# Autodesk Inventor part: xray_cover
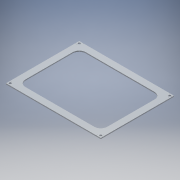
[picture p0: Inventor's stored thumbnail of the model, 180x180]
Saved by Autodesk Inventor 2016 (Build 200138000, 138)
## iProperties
Created: 2015-11
Part Number: xray_cover
Material: Generic
Document SubType Name: Modeling
Designer: t_silvdo
Density: 1 g/cm^3
Appearance: Default
Author: t_silvdo
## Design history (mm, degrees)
sketch "Sketch2"
  geometry: L1 (0, 0)-(279.4, 0); L2 (279.4, 0)-(279.4, -215.9); L3 (279.4, -215.9)-(0, -215.9); L4 (0, -215.9)-(0, 0); C1 r 3.175 at (273.05, -6.35); C2 r 3.175 at (273.05, -209.55); C3 r 3.175 at (6.35, -6.35); C4 r 3.175 at (6.35, -209.55); 1 further point
  constraints: 8 end point, 4 centre point, 2 parallel, 1 horizontal, 1 perpendicular
  dimensions: "d7" = 279.4 distance of L2.end L3.end; "d8" = 215.9 distance of L1.end L2.end; "d9" = 6.35 diameter of C1; "d10" = 6.35 distance from line of C1.centre L1; "d11" = 6.35 distance from line of C1.centre L2
extrude "Extrusion2" new body sketch "Sketch2" distance "d12" = 3 (= acrylic); taper "d13" = 0 deg
sketch "Sketch3"
  geometry: L1 (-279.4, 0)-(0, 0) reference; L2 (0, 0)-(0, 215.9) reference; L3 (0, 215.9)-(-279.4, 215.9) reference; L4 (-279.4, 215.9)-(-279.4, 0) reference; L5 (-38.1, 19.05)-(-241.3, 19.05); L6 (-260.35, 38.1)-(-260.35, 177.8); L7 (-241.3, 196.85)-(-38.1, 196.85); L8 (-19.05, 177.8)-(-19.05, 38.1); L9 (-19.05, 19.05)-(-260.35, 196.85); L10 (-260.35, 19.05)-(-19.05, 196.85); C1 r 3.175 at (-6.35, 209.55) reference; C2 r 3.175 at (-6.35, 6.35) reference; C3 r 3.175 at (-273.05, 209.55) reference; C4 r 3.175 at (-273.05, 6.35) reference; A1 r 19.05 centre (-241.3, 38.1) between (-260.35, 38.1) and (-241.3, 19.05); A2 r 19.05 centre (-241.3, 177.8) between (-241.3, 196.85) and (-260.35, 177.8); A3 r 19.05 centre (-38.1, 177.8) between (-19.05, 177.8) and (-38.1, 196.85); A4 r 19.05 centre (-38.1, 38.1) between (-38.1, 19.05) and (-19.05, 38.1); 2 further points
  constraints: 12 end point, 8 point on circle, 8 point on line, 8 tangent, 4 centre point, 3 equal radius, 2 midpoint, 2 parallel, 1 horizontal, 1 perpendicular
  dimensions: "d14" = 241.3 distance of L9.end L10.end; "d15" = 177.8 distance of L10.start L9.end; "d16" = 19.05 radius of A1
extrude "Extrusion3" cut sketch "Sketch3" distance "d17" = 25.4; taper "d18" = 0 deg
sketch "Sketch5"
  geometry: L1 (-260.35, 38.1)-(-260.35, 177.8) reference; L2 (-241.3, 196.85)-(-38.1, 196.85) reference; L3 (-19.05, 177.8)-(-19.05, 38.1) reference; L4 (-38.1, 19.05)-(-241.3, 19.05) reference; L5 (-279.4, 0)-(0, 0) reference; L6 (0, 0)-(0, 215.9) reference; L7 (0, 215.9)-(-279.4, 215.9) reference; L8 (-279.4, 215.9)-(-279.4, 0) reference; L9 (0, 0)-(0, 215.9) reference; L10 (0, 203.2)-(-4.763, 203.2); L11 (-4.763, 203.2)-(-4.762, 202.946); L12 (-4.762, 202.946)-(0, 202.946); L13 (0, 202.946)-(0, 203.2); L14 (-139.7, 107.95)-(-133.006, 107.95); L15 (-139.7, 107.95)-(-139.7, 101.651); L16 (0, 12.7)-(-4.762, 12.7); L17 (-4.762, 12.7)-(-4.762, 12.954); L18 (-4.762, 12.954)-(0, 12.954); L19 (0, 12.954)-(0, 12.7); L20 (-279.4, 203.2)-(-274.638, 203.2); L21 (-274.638, 203.2)-(-274.638, 202.946); L22 (-274.638, 202.946)-(-279.4, 202.946); L23 (-279.4, 202.946)-(-279.4, 203.2); L24 (-279.4, 215.9)-(-279.4, 0) reference; L25 (-279.4, 12.7)-(-274.637, 12.7); L26 (-274.637, 12.7)-(-274.637, 12.954); L27 (-274.637, 12.954)-(-279.4, 12.954); L28 (-279.4, 12.954)-(-279.4, 12.7); C1 r 3.175 at (-6.35, 209.55) reference; C2 r 3.175 at (-6.35, 6.35) reference; C3 r 3.175 at (-273.05, 209.55) reference; C4 r 3.175 at (-273.05, 6.35) reference; A1 r 19.05 centre (-241.3, 38.1) between (-260.35, 38.1) and (-241.3, 19.05) reference; A2 r 19.05 centre (-241.3, 177.8) between (-241.3, 196.85) and (-260.35, 177.8) reference; A3 r 19.05 centre (-38.1, 177.8) between (-19.05, 177.8) and (-38.1, 196.85) reference; A4 r 19.05 centre (-38.1, 38.1) between (-38.1, 19.05) and (-19.05, 38.1) reference
  constraints: 36 end point, 8 parallel, 5 horizontal, 4 perpendicular, 4 point on line, 1 vertical
  dimensions: "d29" = 4.7625 distance of L12.end L11.end; "d30" = 0.254 distance of L11.end L10.end; "d31" = 6.35 distance from line of C1.centre L10; "d32" = 4.7625 distance of L17.end L18.end; "d33" = 0.254 distance of L16.end L17.end; "d34" = 6.35 distance from line of L16 C2.centre; "d35" = 4.7625 distance of L21.end L22.end; "d36" = 0.254 distance of L20.end L21.end; "d37" = 6.35 distance from line of C3.centre L20; "d38" = 4.7625 distance of L27.end L26.end; "d39" = 0.254 distance of L26.end L25.end; "d40" = 6.35 distance from line of C4.centre L25
extrude "Extrusion5" join sketch "Sketch5" distance "d41" = 0.254; taper "d42" = 0 deg
sketch "Sketch6"
  geometry: L1 (-274.638, 202.946)-(-279.4, 202.946) reference; L2 (-279.4, 202.946)-(-279.4, 12.954) reference; L3 (-279.4, 12.954)-(-274.637, 12.954) reference; L4 (-274.637, 12.954)-(-274.637, 12.7) reference; L5 (-274.637, 12.7)-(-279.4, 12.7) reference; L6 (-279.4, 12.7)-(-279.4, 0) reference; L7 (-279.4, 0)-(0, 0) reference; L8 (0, 0)-(0, 12.7) reference; L9 (0, 12.7)-(-4.762, 12.7) reference; L10 (-4.762, 12.7)-(-4.762, 12.954) reference; L11 (-4.762, 12.954)-(0, 12.954) reference; L12 (0, 12.954)-(0, 202.946) reference; L13 (0, 202.946)-(-4.762, 202.946) reference; L14 (-4.762, 202.946)-(-4.763, 203.2) reference; L15 (-4.763, 203.2)-(0, 203.2) reference; L16 (0, 203.2)-(0, 215.9) reference; L17 (0, 215.9)-(-279.4, 215.9) reference; L18 (-279.4, 215.9)-(-279.4, 203.2) reference; L19 (-279.4, 203.2)-(-274.638, 203.2) reference; L20 (-274.638, 203.2)-(-274.638, 202.946) reference; L21 (-260.35, 38.1)-(-260.35, 177.8) reference; L22 (-241.3, 196.85)-(-38.1, 196.85) reference; L23 (-19.05, 177.8)-(-19.05, 38.1) reference; L24 (-38.1, 19.05)-(-241.3, 19.05) reference; L25 (0, 215.9)-(-279.4, 215.9) reference; L26 (-266.7, 215.9)-(-266.446, 215.9); L27 (-266.446, 215.9)-(-266.446, 211.138); L28 (-266.446, 211.138)-(-266.7, 211.138); L29 (-266.7, 211.138)-(-266.7, 215.9); L30 (-12.7, 215.9)-(-12.954, 215.9); L31 (-12.954, 215.9)-(-12.954, 212.884); L32 (-12.954, 212.884)-(-12.7, 212.884); L33 (-12.7, 212.884)-(-12.7, 215.9); L34 (-279.4, 0)-(0, 0) reference; L35 (-12.954, 0)-(-12.7, 0); L36 (-12.7, 0)-(-12.7, 4.763); L37 (-12.7, 4.763)-(-12.954, 4.763); L38 (-12.954, 4.763)-(-12.954, 0); L39 (-266.7, 0)-(-266.446, 0); L40 (-266.446, 0)-(-266.446, 4.763); L41 (-266.446, 4.763)-(-266.7, 4.763); L42 (-266.7, 4.763)-(-266.7, 0); C1 r 3.175 at (-6.35, 209.55) reference; C2 r 3.175 at (-6.35, 6.35) reference; C3 r 3.175 at (-273.05, 209.55) reference; C4 r 3.175 at (-273.05, 6.35) reference; A1 r 19.05 centre (-241.3, 38.1) between (-260.35, 38.1) and (-241.3, 19.05) reference; A2 r 19.05 centre (-241.3, 177.8) between (-241.3, 196.85) and (-260.35, 177.8) reference; A3 r 19.05 centre (-38.1, 177.8) between (-19.05, 177.8) and (-38.1, 196.85) reference; A4 r 19.05 centre (-38.1, 38.1) between (-38.1, 19.05) and (-19.05, 38.1) reference
  constraints: 32 end point, 8 parallel, 4 horizontal, 4 perpendicular, 4 point on line
  dimensions: "d43" = 0.254 distance of L27.end L28.end; "d44" = 4.7625 distance of L26.end L27.end; "d45" = 6.35 distance from line of L29 C3.centre; "d46" = 0.254 distance of L32.end L31.end; "d47" = 3.01625 distance of L31.end L30.end; "d48" = 0.254 distance of L37.end L36.end; "d49" = 4.7625 distance of L36.end L35.end; "d50" = 6.35 distance from line of C1.centre L33; "d51" = 6.35 distance from line of C2.centre L36; "d52" = 0.254 distance of L41.end L40.end; "d53" = 4.7625 distance of L40.end L39.end; "d54" = 6.35 distance from line of L42 C4.centre
extrude "Extrusion6" join sketch "Sketch6" distance "d55" = 0.254; taper "d56" = 0 deg
body "Solid2"
node "Projected Loop1"
node "Projected Loop3"
node "Projected Loop4"
other parameters: "acrylic" = 3 [user parameter; used in 1 equation term], "t" = 0.381 [user parameter]
